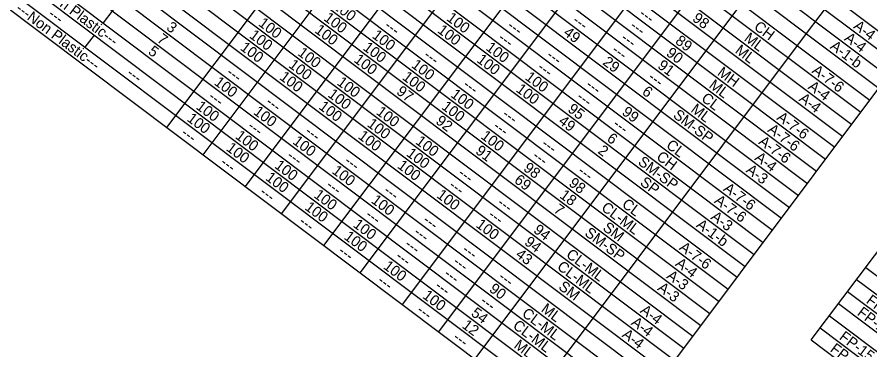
# Model space of a CAD drawing. Extents: x 627484.2 to 627514.4, y 367972.1 to 367996.9.
# Drawn here: x 627486.414 to 627490.816, y 367989.162 to 367990.878 of the extents above; entities that cross this region are included whole.
import ezdxf

# ---------------------------------------------------------------- set-up
doc = ezdxf.new("R2010")
doc.units = 0
doc.layers.add('Default', color=7, linetype='Continuous')

msp = doc.modelspace()

# ---------------------------------------------------------------- linework, layer by layer
at = {"layer": 'Default'}
for p, q in [((627487.187, 367990.3091), (627490.4568, 367994.6635)), ((627485.764, 367994.6332), (627491.0034, 367990.6988)), ((627485.7172, 367994.5708), (627490.9566, 367990.6365)), ((627485.6703, 367994.5084), (627490.9097, 367990.5741)), ((627485.6235, 367994.4461), (627490.8629, 367990.5117)), ((627485.5767, 367994.3837), (627490.8161, 367990.4494)), ((627485.5298, 367994.3213), (627490.7692, 367990.387)), ((627485.483, 367994.2589), (627490.7224, 367990.3246)), ((627485.4362, 367994.1966), (627490.6756, 367990.2622)), ((627485.3952, 367994.142), (627490.6346, 367990.2077)), ((627485.3483, 367994.0796), (627490.5877, 367990.1453)), ((627485.3015, 367994.0172), (627490.5409, 367990.0829)), ((627485.2547, 367993.9549), (627490.4941, 367990.0205)), ((627485.2078, 367993.8925), (627490.4472, 367989.9582)), ((627485.161, 367993.8301), (627490.4004, 367989.8958)), ((627485.12, 367993.7755), (627490.3594, 367989.8412)), ((627485.0732, 367993.7132), (627490.3126, 367989.7788)), ((627485.0263, 367993.6508), (627490.2657, 367989.7165)), ((627484.9795, 367993.5884), (627490.2189, 367989.6541)), ((627484.9327, 367993.5261), (627490.1721, 367989.5917)), ((627484.8917, 367993.4715), (627490.1311, 367989.5372)), ((627484.8448, 367993.4091), (627490.0843, 367989.4748)), ((627484.798, 367993.3467), (627490.0374, 367989.4124)), ((627484.7512, 367993.2844), (627489.9906, 367989.35)), ((627490.4887, 367990.7927), (627492.3241, 367993.237)), ((627484.7043, 367993.222), (627489.9437, 367989.2877)), ((627484.6634, 367993.1674), (627489.9028, 367989.2331)), ((627484.6165, 367993.105), (627489.8559, 367989.1707)), ((627484.5697, 367993.0427), (627489.8091, 367989.1083)), ((627484.5228, 367992.9803), (627489.7623, 367989.046)), ((627484.4819, 367992.9257), (627489.7213, 367988.9914)), ((627484.435, 367992.8633), (627489.6744, 367988.929)), ((627484.3882, 367992.801), (627489.6276, 367988.8666)), ((627484.3414, 367992.7386), (627489.5808, 367988.8043)), ((627484.2945, 367992.6762), (627489.5339, 367988.7419)), ((627484.2477, 367992.6139), (627489.4871, 367988.6795)), ((627484.2008, 367992.5515), (627489.4403, 367988.6172)), ((627487.3742, 367990.1686), (627488.7968, 367992.0632)), ((627486.8598, 367990.8475), (627487.7262, 367992.0014)), ((627487.5925, 367990.0047), (627489.0151, 367991.8993)), ((627487.7796, 367989.8642), (627489.2022, 367991.7587)), ((627487.9979, 367989.7002), (627489.4205, 367991.5948)), ((627488.185, 367989.5597), (627489.6077, 367991.4543)), ((627488.4033, 367989.3958), (627489.826, 367991.2904)), ((627488.5904, 367989.2553), (627490.0131, 367991.1499)), ((627488.7775, 367989.1148), (627490.2002, 367991.0094)), ((627486.7661, 367990.7228), (627486.8129, 367990.7851)), ((627489.066, 367988.8982), (627490.4887, 367990.7927)), ((627489.4403, 367988.6172), (627490.9039, 367990.5663)), ((627490.5134, 367989.2135), (627491.1222, 367990.0244)), ((627490.7944, 367989.5878), (627496.0338, 367985.6534)), ((627490.7475, 367989.5254), (627495.9869, 367985.5911)), ((627490.7007, 367989.463), (627495.9401, 367985.5287)), ((627490.6539, 367989.4007), (627495.8933, 367985.4663)), ((627490.607, 367989.3383), (627495.8464, 367985.404)), ((627490.5602, 367989.2759), (627495.7996, 367985.3416)), ((627490.5134, 367989.2135), (627495.7528, 367985.2792))]:
    msp.add_line(p, q, dxfattribs=at)

# ---------------------------------------------------------------- texts
for s, p in [('---Non Plastic---', (627486.4964, 367991.0372)), ('100', (627488.0398, 367990.9268)), ('---Non Plastic---', (627486.4027, 367990.9125)), ('---', (627486.5703, 367990.8842)), ('100', (627487.993, 367990.8644)), ('100', (627488.6267, 367990.8641)), ('---', (627489.6201, 367990.8863)), ('98', (627489.8956, 367990.8623)), ('3', (627487.1807, 367990.816)), ('100', (627487.6556, 367990.8373)), ('---', (627489.2769, 367990.8514)), ('CH', (627490.2132, 367990.8189)), ('A-4', (627490.727, 367990.8233)), ('100', (627487.9461, 367990.8021)), ('---', (627488.3057, 367990.8247)), ('100', (627488.5799, 367990.8017)), ('---', (627488.9395, 367990.8243)), ('49', (627489.2301, 367990.789)), ('---', (627489.5732, 367990.8239)), ('7', (627487.1326, 367990.7545)), ('100', (627487.6088, 367990.775)), ('100', (627488.2425, 367990.7746)), ('---', (627488.8927, 367990.7619)), ('---', (627489.5264, 367990.7615)), ('89', (627489.8073, 367990.7457)), ('ML', (627490.1628, 367990.7592)), ('A-4', (627490.6801, 367990.7609)), ('5', (627487.0865, 367990.6917)), ('100', (627487.5619, 367990.7126)), ('100', (627488.1957, 367990.7122)), ('100', (627488.8294, 367990.7119)), ('90', (627489.7602, 367990.6835)), ('ML', (627490.116, 367990.6968)), ('A-1-b', (627490.6063, 367990.7188)), ('100', (627487.8583, 367990.6851)), ('100', (627488.1488, 367990.6499)), ('---', (627488.5085, 367990.6724)), ('100', (627488.7826, 367990.6495)), ('---', (627489.1422, 367990.6721)), ('---', (627489.4796, 367990.6992)), ('100', (627487.8115, 367990.6228)), ('100', (627488.4452, 367990.6224)), ('29', (627489.4328, 367990.6368)), ('91', (627489.7162, 367990.619)), ('---', (627486.9757, 367990.5797)), ('---', (627487.4905, 367990.5833)), ('100', (627487.7646, 367990.5604)), ('100', (627488.3984, 367990.56)), ('100', (627489.0321, 367990.5596)), ('---', (627489.0954, 367990.6097)), ('MH', (627490.0245, 367990.5826)), ('A-7-6', (627490.5127, 367990.594)), ('100', (627487.4273, 367990.5333)), ('100', (627488.061, 367990.5329)), ('---', (627489.6667, 367990.5587)), ('ML', (627489.9813, 367990.5175)), ('100', (627488.0142, 367990.4705)), ('97', (627488.3681, 367990.4852)), ('100', (627488.6479, 367990.4702)), ('---', (627488.7112, 367990.5202)), ('100', (627488.9853, 367990.4973)), ('---', (627489.3449, 367990.5199)), ('6', (627489.636, 367990.4841)), ('A-4', (627490.4928, 367990.5114)), ('---', (627487.3968, 367990.4586)), ('---', (627489.2981, 367990.4575)), ('CL', (627489.9417, 367990.4497)), ('A-4', (627490.446, 367990.449)), ('100', (627487.3336, 367990.4085)), ('100', (627487.63, 367990.3811)), ('---', (627487.6932, 367990.4311)), ('100', (627487.9673, 367990.4082)), ('100', (627488.2637, 367990.3807)), ('100', (627488.6011, 367990.4078)), ('95', (627489.2521, 367990.3945)), ('99', (627489.5321, 367990.3793)), ('ML', (627489.8876, 367990.3928)), ('100', (627487.2868, 367990.3462)), ('92', (627488.5707, 367990.3331)), ('---', (627488.9139, 367990.368)), ('SM-SP', (627489.7961, 367990.3639)), ('A-7-6', (627490.3312, 367990.3523)), ('---', (627487.5995, 367990.3064)), ('100', (627488.2169, 367990.3183)), ('49', (627489.2045, 367990.3327)), ('---', (627489.4852, 367990.317)), ('---', (627487.2563, 367990.2715)), ('100', (627487.5363, 367990.2563)), ('---', (627487.8959, 367990.2789)), ('100', (627488.1701, 367990.2559)), ('100', (627488.8038, 367990.2556)), ('---', (627488.867, 367990.3056)), ('A-7-6', (627490.2844, 367990.2899)), ('100', (627487.8327, 367990.2288)), ('100', (627488.4664, 367990.2285)), ('6', (627489.4545, 367990.2425)), ('CL', (627489.7602, 367990.208)), ('A-7-6', (627490.2375, 367990.2276)), ('100', (627487.4895, 367990.1939)), ('100', (627488.4196, 367990.1661)), ('91', (627488.776, 367990.1789)), ('---', (627489.1166, 367990.2158)), ('2', (627489.4078, 367990.18)), ('---', (627487.8023, 367990.1542)), ('---', (627489.0698, 367990.1534)), ('SM-SP', (627489.6146, 367990.1223)), ('CH', (627489.7097, 367990.1484)), ('A-4', (627490.2176, 367990.145)), ('---', (627487.459, 367990.1193)), ('100', (627487.739, 367990.1041)), ('100', (627488.0354, 367990.0766)), ('---', (627488.0986, 367990.1267)), ('100', (627488.3728, 367990.1037)), ('98', (627489.0235, 367990.0906)), ('A-3', (627490.1724, 367990.0814)), ('100', (627487.6922, 367990.0417)), ('---', (627488.6856, 367990.0639)), ('69', (627488.9762, 367990.0286)), ('---', (627489.3037, 367990.0753)), ('---', (627488.005, 367990.0019)), ('---', (627488.6387, 367990.0016)), ('98', (627489.2574, 367990.0125)), ('SP', (627489.6255, 367990.0165)), ('A-7-6', (627490.056, 367989.9859)), ('---', (627487.6618, 367989.967)), ('100', (627487.9417, 367989.9519)), ('---', (627488.3014, 367989.9745)), ('100', (627488.5755, 367989.9515)), ('18', (627489.2106, 367989.9501)), ('100', (627488.2381, 367989.9244)), ('---', (627488.8883, 367989.9117)), ('CL', (627489.5319, 367989.9039)), ('A-7-6', (627490.0092, 367989.9235)), ('100', (627487.8949, 367989.8895)), ('7', (627489.1796, 367989.8759)), ('CL-ML', (627489.4255, 367989.8863)), ('---', (627488.2077, 367989.8497)), ('---', (627488.5041, 367989.8222)), ('---', (627488.8414, 367989.8493)), ('A-3', (627489.9909, 367989.8397)), ('---', (627487.8645, 367989.8148)), ('100', (627488.1444, 367989.7997)), ('100', (627488.7782, 367989.7993)), ('94', (627489.0752, 367989.7714)), ('SM', (627489.4328, 367989.7833)), ('A-1-b', (627489.9154, 367989.7988)), ('100', (627488.0976, 367989.7373)), ('---', (627488.4572, 367989.7599)), ('SM-SP', (627489.3395, 367989.7558)), ('---', (627488.4104, 367989.6975)), ('94', (627489.0284, 367989.709)), ('A-7-6', (627489.8277, 367989.6818)), ('---', (627488.0672, 367989.6626)), ('---', (627488.7068, 367989.67)), ('43', (627488.9831, 367989.6454)), ('CL-ML', (627489.244, 367989.6446)), ('---', (627488.3636, 367989.6351)), ('---', (627488.6599, 367989.6077)), ('A-4', (627489.8078, 367989.5992)), ('100', (627488.3003, 367989.5851)), ('CL-ML', (627489.1972, 367989.5822)), ('---', (627488.6131, 367989.5453)), ('---', (627488.8939, 367989.5295)), ('A-3', (627489.7626, 367989.5356)), ('---', (627488.2699, 367989.5104)), ('---', (627488.5663, 367989.4829)), ('90', (627488.8469, 367989.4673)), ('SM', (627489.2044, 367989.4792)), ('A-3', (627489.7157, 367989.4733)), ('100', (627488.503, 367989.4329)), ('FP-14', (627490.7932, 367989.4079)), ('---', (627488.8002, 367989.4048)), ('ML', (627489.1148, 367989.3636)), ('---', (627488.4726, 367989.3582)), ('54', (627488.7532, 367989.3425)), ('CL-ML', (627489.0157, 367989.3405)), ('A-4', (627489.6263, 367989.3575)), ('FP-14', (627490.7464, 367989.3455)), ('12', (627488.7066, 367989.28)), ('CL-ML', (627488.9689, 367989.2781)), ('A-4', (627489.5795, 367989.2951)), ('---', (627488.6597, 367989.2177)), ('A-4', (627489.5327, 367989.2328)), ('FP-15', (627490.6537, 367989.22)), ('ML', (627488.9743, 367989.1765)), ('FP-15', (627490.6069, 367989.1577))]:
    msp.add_text(s, height=0.055, rotation=323.0968, dxfattribs=at).set_placement(p)

doc.saveas('drawing.dxf')
